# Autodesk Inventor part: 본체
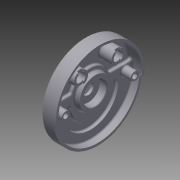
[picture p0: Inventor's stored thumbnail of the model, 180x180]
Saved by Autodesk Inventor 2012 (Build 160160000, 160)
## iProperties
Created: 2015-04
Part Number: 본체
Material: 알루미늄-6061
Document SubType Name: Modeling
Designer: Owner
Density: 2.71 g/cm^3
Mass: 899.843 g
Surface Area: 1054.84 cm^2
Volume: 332.045 cm^3
Author: Owner
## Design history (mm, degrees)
sketch "스케치2"
  geometry: C1 r 95 at (0, 0); 1 further point
  constraints: 1 centre point, 1 coincident
  dimensions: "d3" = 190 diameter of C1
extrude "돌출1" new body sketch "스케치2" distance "d4" = 32; taper "d5" = 0 deg
sketch "스케치3"
  geometry: C1 r 95 at (0, 0) reference; C2 r 90 at (0, 0)
  constraints: 1 centre point, 1 coincident
  dimensions: "d6" = 180 diameter of C2
extrude "돌출2" cut sketch "스케치3" distance "d7" = 20.5; taper "d8" = 0 deg
sketch "스케치4"
  geometry: L1 (-79.667, -14)-(79.667, -14); C1 r 90 at (0, 0) reference; C2 r 90 at (0, 0) reference; C3 r 90 at (0, 0) reference; C4 r 95 at (0, 0) reference; A1 r 41 centre (0, -14) between (-41, -14) and (41, -14); A2 r 59 centre (0, -14) between (-59, -14) and (59, -14); A3 r 9 centre (-50, -14) between (-41, -14) and (-59, -14); A4 r 9 centre (50, -14) between (59, -14) and (41, -14); 1 further point
  constraints: 8 point on circle, 4 centre point, 2 coincident, 2 end point, 2 point on line, 2 tangent, 1 horizontal, 1 midpoint, 1 vertical alignment
  dimensions: "d9" = 14 distance from line of C1.centre L1; "d10" = 82 diameter of A1; "d11" = 118 diameter of A2; "d12" = 18 diameter of A3; "d13" = 18 diameter of A4
extrude "돌출3" cut sketch "스케치4" distance "d14" = 7; taper "d15" = 0 deg
sketch "스케치5"
  geometry: L1 (-83.283, 12)-(83.283, 12); C1 r 90 at (0, 0) reference; A1 r 42 centre (0, 0) between (40.249, 12) and (-40.249, 12); A2 r 5 centre (-83.283, 17) between (-88.182, 18) and (-83.283, 12); A3 r 5 centre (83.283, 17) between (83.283, 12) and (88.182, 18); A4 r 90 centre (0, 0) between (-88.182, 18) and (88.182, 18) reference; A5 r 5 centre (-43.818, 17) between (-43.818, 12) and (-39.156, 15.191); A6 r 5 centre (43.818, 17) between (39.156, 15.191) and (43.818, 12); A7 r 90 centre (0, 0) between (88.182, 18) and (-88.182, 18)
  constraints: 16 point on circle, 8 tangent, 6 centre point, 4 point on line, 2 coincident, 2 end point, 1 horizontal
  dimensions: "d16" = 84 diameter of A1; "d17" = 12 distance from line of L1 A1.centre; "d18" = 10 diameter of A2; "d19" = 10 diameter of A3; "d20" = 10 diameter of A5; "d21" = 10 diameter of A6
extrude "돌출4" cut sketch "스케치5" distance "d22" = 7; taper "d23" = 0 deg
sketch "스케치6"
  geometry: L1 (-83.283, 12)-(-43.818, 12) reference; L2 (-56.202, 52)-(58.852, 52); L3 (0, 0)-(0, 134.318); C1 r 15 at (-40, 52); A1 r 42 centre (0, 0) between (39.156, 15.191) and (-39.156, 15.191) reference; A2 r 90 centre (0, 0) between (88.182, 18) and (-88.182, 18) reference
  constraints: 4 end point, 1 centre point, 1 parallel, 1 perpendicular, 1 point on line
  dimensions: "d24" = 52 distance from line of L2 A1.centre; "d25" = 30 diameter of C1; "d26" = 40 distance from line of L3 C1.centre
extrude "돌출5" join sketch "스케치6" distance "d27" = 26.5; taper "d28" = 0 deg
sketch "스케치7"
  geometry: C1 r 15 at (0, 0) reference; C2 r 10 at (0, 0); 1 further point
  constraints: 1 centre point, 1 coincident
  dimensions: "d29" = 20 diameter of C2
extrude "돌출6" cut sketch "스케치7" stored distance "d30" = 30.5; taper "d31" = 0 deg
sketch "스케치8"
  geometry: L1 (6, 13.748)-(6, 8); L2 (6, -8)-(6, -13.748); L3 (0, 15)-(0, 10); L4 (0, -10)-(0, -15); L5 (-6, 13.748)-(-6, 8); L6 (-6, -8)-(-6, -13.748); C1 r 10 at (0, 0) reference; C2 r 15 at (0, 0) reference; A1 r 10 centre (0, 0) between (6, 8) and (6, -8); A2 r 15 centre (0, 0) between (-6, 13.748) and (0, 15); 4 further points
  constraints: 12 end point, 12 point on circle, 8 parallel, 3 coincident, 2 centre point, 2 concentric, 2 midpoint, 2 vertical, 2 vertical alignment
  dimensions: "d34" = 6 distance between parallel lines of L5 L3; "d35" = 6 distance between parallel lines of L3 L1; "d36" = 6 distance between parallel lines of L4 L2; "d37" = 6 distance between parallel lines of L6 L4
extrude "돌출7" cut sketch "스케치8" distance "d38" = 3; taper "d39" = 0 deg
sketch "스케치9"
  geometry: C1 r 35 at (0, 0); A1 r 90 centre (0, 0) between (-88.182, 18) and (88.182, 18) reference
  constraints: 1 centre point, 1 coincident
  dimensions: "d40" = 70 diameter of C1
extrude "돌출8" join sketch "스케치9" distance "d41" = 10; taper "d42" = -10 deg
hole "구멍1" diameter "d45" = 23; stored, may be unused: countersink angle "d49" = 90 deg, drill point angle "d51" = 118 deg; dims "d43" = 10, "d44" = 10, "d46" = 6, "d47" = 50, "d48" = 15, "d50" = 8
sketch "스케치10"
  geometry: L1 (-43.818, 12)-(-83.283, 12) reference; L2 (-83.283, 0)-(79.95, 0); C1 r 9 at (-74, 0); C2 r 9 at (74, 0); A1 r 90 centre (0, 0) between (-88.182, 18) and (88.182, 18) reference; A2 r 15 centre (-40, 52) between (-46, 65.748) and (-46, 38.252) reference; A3 r 74 centre (0, 0) between (-74, 0) and (74, 0)
  constraints: 3 centre point, 2 end point, 2 point on circle, 2 point on line, 1 coincident, 1 parallel
  dimensions: "d52" = 52 distance from line of A2.centre L2; "d53" = 148 diameter of A3; "d54" = 18 diameter of C1; "d55" = 18 diameter of C2
extrude "돌출9" join sketch "스케치10" distance "d56" = 21; taper "d57" = 0 deg
hole "구멍2" diameter "d60" = 11; stored, may be unused: countersink angle "d64" = 90 deg, drill point angle "d66" = 0 deg; dims "d58" = 10, "d59" = 10, "d61" = 6, "d62" = 18, "d63" = 15, "d65" = 11
sketch "스케치11"
  geometry: C1 r 5.5 at (74, 0) reference; C2 r 9 at (74, 0)
  constraints: 1 centre point, 1 coincident
  dimensions: "d67" = 18 diameter of C2
extrude "돌출10" cut sketch "스케치11" distance "d68" = 11; taper "d69" = 0 deg
sketch "스케치12"
  geometry: C1 r 9 at (0, 0) reference; C2 r 5.5 at (0, 0); 1 further point
  constraints: 1 centre point, 1 coincident
  dimensions: "d70" = 11 diameter of C2
extrude "돌출11" cut sketch "스케치12" stored distance "d71" = 11; taper "d72" = 0 deg
sketch "스케치13"
  geometry: C1 r 5.5 at (-74, 0) reference; C2 r 9 at (-74, 0)
  constraints: 1 centre point, 1 coincident
  dimensions: "d73" = 18 diameter of C2
extrude "돌출12" cut sketch "스케치13" distance "d74" = 11; taper "d75" = 0 deg
sketch "스케치14"
  geometry: L1 (0, 0)-(0, -72); L2 (0, 0)-(-8.132, -8.132); L3 (-36.062, -36.062)-(-50.912, -50.912); L4 (0, 0)-(8.132, -8.132); L5 (36.062, -36.062)-(50.912, -50.912); C1 r 95 at (0, 0) reference; A1 r 11.5 centre (0, 0) between (-8.132, -8.132) and (8.132, -8.132) reference; A2 r 72 centre (0, 0) between (0, -72) and (-50.912, -50.912); A3 r 51 centre (0, 0) between (-36.062, -36.062) and (36.062, -36.062)
  constraints: 10 end point, 7 point on circle, 2 centre point, 2 coincident, 1 vertical
  dimensions: "d76" = 144 diameter of A2; "d77" = 102 diameter of A3; "d80" = 45 deg angle of L1 L5; "d81" = 45 deg angle of L1 L3
extrude "돌출13" join sketch "스케치14" distance "d82" = 5; taper "d83" = 0 deg
sketch "스케치15"
  geometry: C1 r 88 at (0, 0); A1 r 72 centre (0, 0) between (-50.912, -50.912) and (50.912, -50.912) reference; A2 r 51 centre (0, 0) between (-36.062, -36.062) and (36.062, -36.062) reference
  constraints: 1 centre point, 1 coincident, 1 other
  dimensions: "d84" = 176 diameter of C1
extrude "돌출14" join sketch "스케치15" distance "d85" = 0.5; taper "d86" = 0 deg
fillet "모깎기1" dims "d87" = 5
fillet "모깎기2" dims "d88" = 4
chamfer "모따기1" distance "d89" = 1; stored, may be unused: second distance "d90" = 2, angle "d91" = 45 deg
chamfer "모따기2" distance "d92" = 1; stored, may be unused: second distance "d93" = 2, angle "d94" = 45 deg
fillet "모깎기3" dims "d95" = 5
sketch "스케치16"
  geometry: L1 (-95, 0)-(95, 0); L2 (0, 0)-(-94.638, -8.28); L3 (0, 0)-(94.638, -8.28); C1 r 90 at (0, 0) reference; A1 r 95 centre (0, 0) between (-94.638, -8.28) and (94.638, -8.28) reference; A2 r 95 centre (0, 0) between (95, 0) and (-95, 0); A3 r 95 centre (0, 0) between (-94.638, -8.28) and (94.638, -8.28); A4 r 90 centre (0, 0) between (90, 0) and (-90, 0); A5 r 90 centre (0, 0) between (-89.658, -7.844) and (89.658, -7.844)
  constraints: 10 point on circle, 6 end point, 4 centre point, 4 point on line, 3 coincident, 1 horizontal
  dimensions: "d96" = 5 deg angle of L1 L2; "d97" = 5 deg angle of L1 L3
extrude "돌출15" cut sketch "스케치16" distance "d98" = 5; taper "d99" = 0 deg
fillet "모깎기4" dims "d100" = 3
fillet "모깎기5" dims "d101" = 0.3
fillet "모깎기6" dims "d102" = 3
fillet "모깎기7" dims "d103" = 3
fillet "모깎기8" dims "d104" = 3
fillet "모깎기9" dims "d105" = 3
fillet "모깎기10" dims "d106" = 3
fillet "모깎기11" dims "d107" = 1
node "솔리드2"
mirror "대칭1"
node "투영된 루프1"
other parameters: "d32" = 6, "d33" = 6, "d78" = 45 deg, "d79" = 45 deg
